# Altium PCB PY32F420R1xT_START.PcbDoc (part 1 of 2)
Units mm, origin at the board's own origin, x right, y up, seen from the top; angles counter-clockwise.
Board outline 45 x 98.2 mm, 2 copper layers (Top Layer, Bottom Layer), stack 0.533 mm thick; 144 components, 163 nets, 571 pads, 318 vias.
Unrouted connection lines stored in the file: 5.
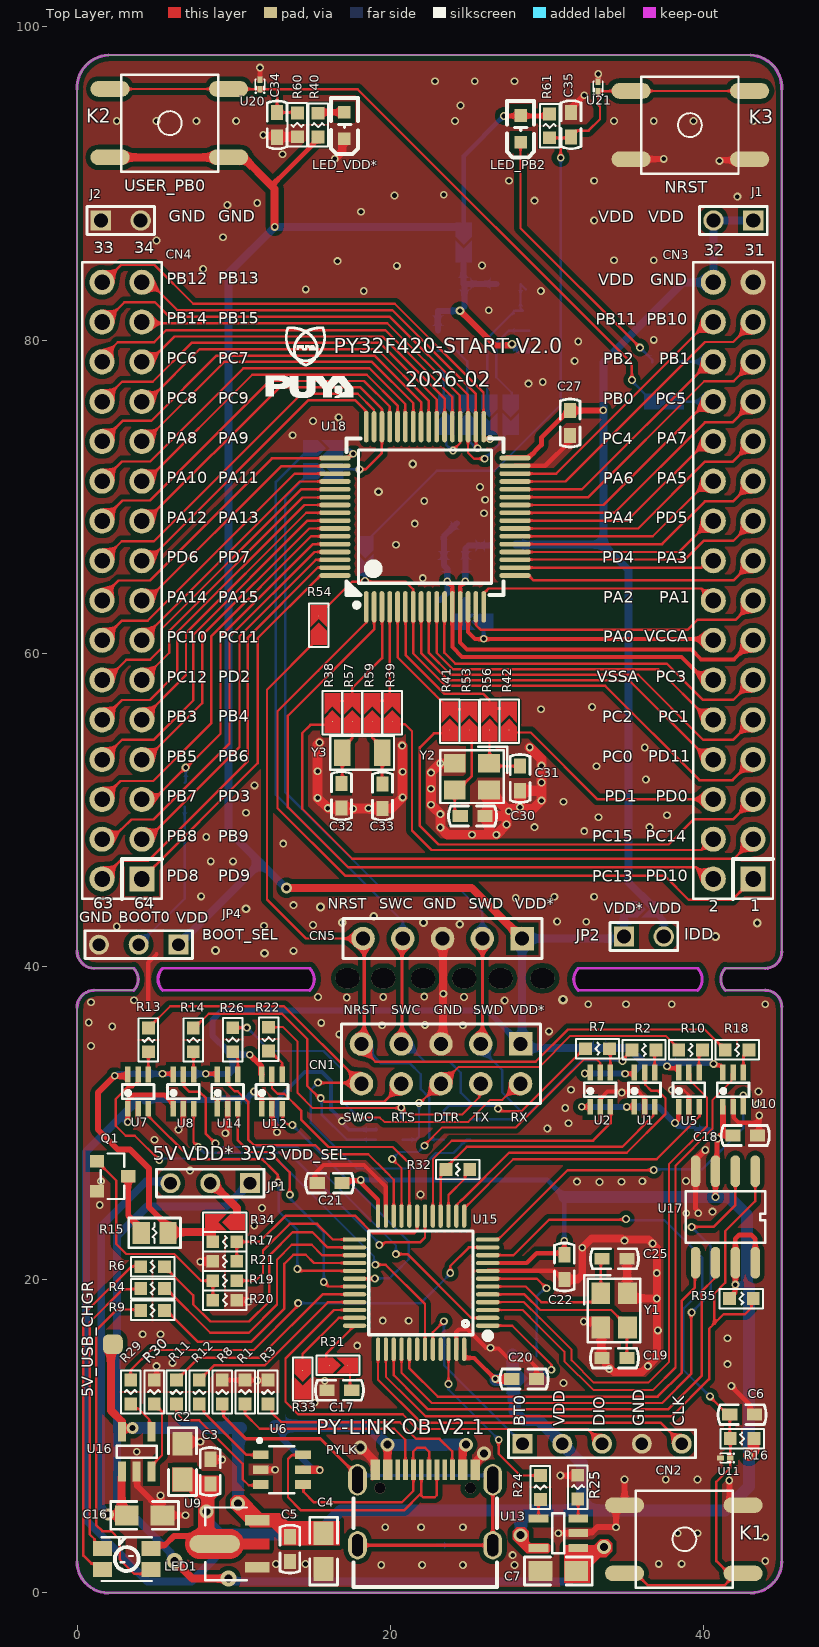
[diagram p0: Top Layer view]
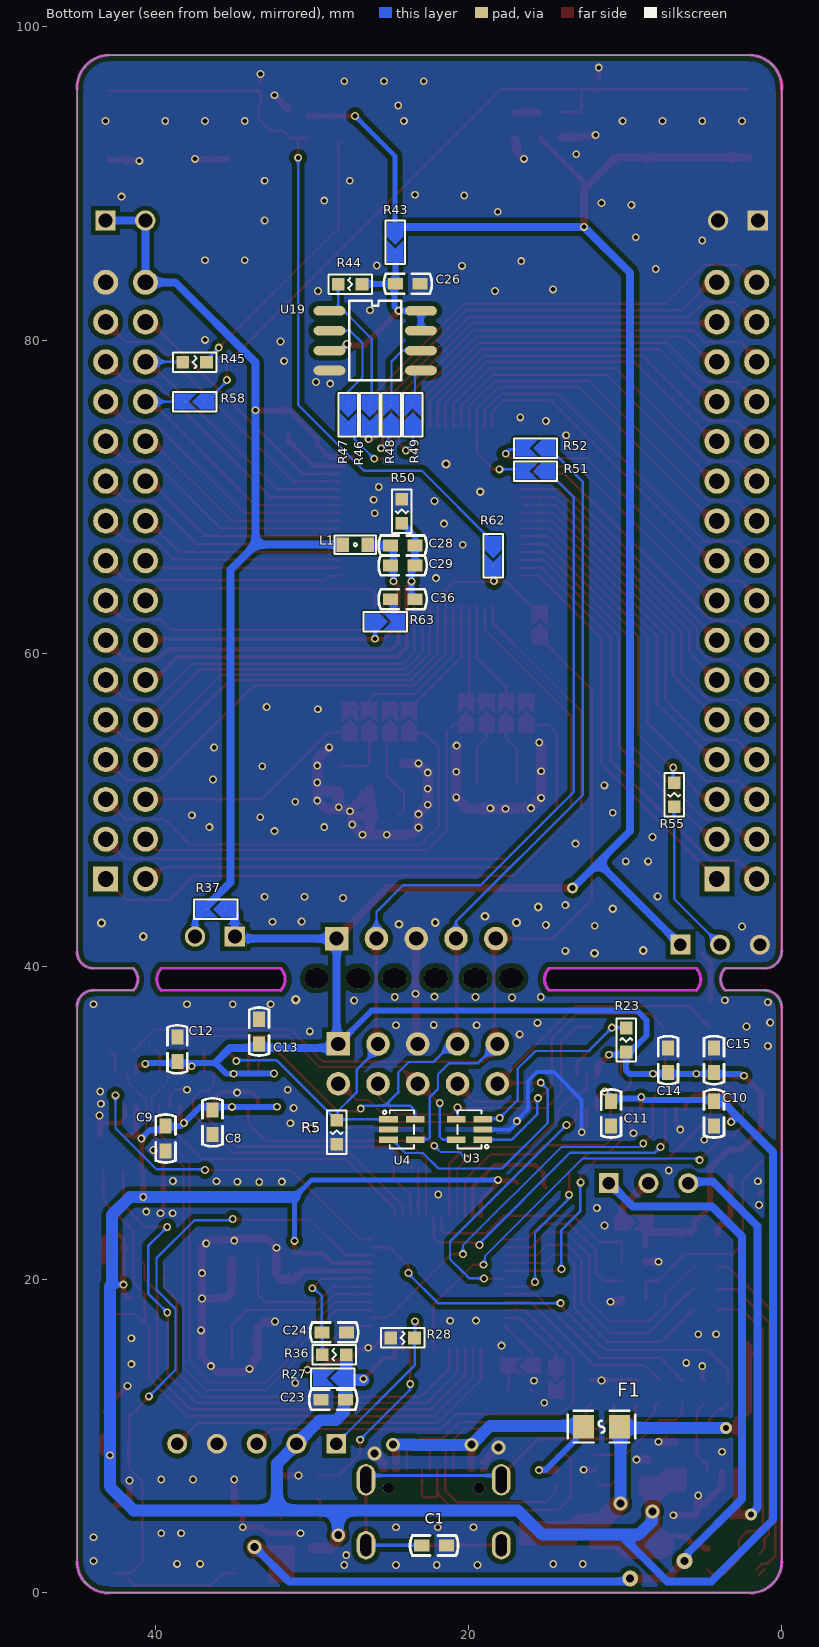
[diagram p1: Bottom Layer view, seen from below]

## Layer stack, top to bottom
Top Solder: solder mask 0.0102, Solder Resist, Dk 3.5
Top Layer: signal copper 0.0356
Dielectric 2: prepreg 0.0711, Composite dielectric, Dk 4.1
Dielectric 1: prepreg 0.32, Composite dielectric, Dk 4.1
Dielectric 3: prepreg 0.0711, Composite dielectric, Dk 4.1
Bottom Layer: signal copper 0.0356
Bottom Solder: solder mask 0.0102, Solder Resist, Dk 3.5

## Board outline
0,2 0,37.338 cw(c1.111,37.37) 1.079,38.481 3.619,38.481 ccw(c2.921,39.179) 3.619,39.878 1.079,39.878 cw(c1.111,40.989) 0,41.021 0,96 cw(c2.099,96.099) 2,98.198 43,98.198 cw(c42.901,96.099) 45,96 45,40.936 cw(c43.942,40.936) 43.942,39.878 41.402,39.878 ccw(c42.1,39.179) 41.402,38.481 43.942,38.481 cw(c43.942,37.423) 45,37.423 45,2 cw(c43,2) 43,0 2,0 cw(c2,2)
cut-out: 5.461,38.481 cw(c6.159,39.179) 5.461,39.878 14.859,39.878 cw(c14.16,39.179) 14.859,38.481 14.351,38.481
cut-out: 32.004,38.481 cw(c32.703,39.179) 32.004,39.878 39.624,39.878 cw(c38.925,39.179) 39.624,38.481

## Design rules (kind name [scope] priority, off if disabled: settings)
Clearance polygon [InPolygon] p1: gap=0.305 ignorepadtopadclearanceinfootprint=TRUE
Clearance [All] p2: gap=0.178 ignorepadtopadclearanceinfootprint=TRUE
HoleToHoleClearance [All] p1: gap=0.025 allowstackedmicrovias=TRUE
MinimumSolderMaskSliver [All] p1: minsoldermaskwidth=0
PlaneClearance [All] p1: clearance=0.203
PlaneConnect [All] p1: planeconnectstyle=Direct reliefexpansion=0.508 reliefentries=4 reliefconductorwidth=0.254 reliefairgap=0.254
PolygonConnect [All] p1: connectstyle=Direct reliefconductorwidth=0.254 reliefentries=4 polygonreliefangle="90 Angle" airgapwidth=0.254
RoutingVias [All] p1: holewidth=0.711 width=1.27 viastyle="Through Hole" minholewidth=0.711 minwidth=1.27 maxholewidth=0.711 maxwidth=1.27
SilkToSilkClearance [All] p1: silktosilkclearance=0
SilkToSolderMaskClearance [IsPad] p1: minsilkscreentomaskgap=0 clearancetoexposedcopper=TRUE
SolderMaskExpansion [All] p1: expansion=0.102 istentingtop=FALSE
UnRoutedNet [All] p1: checkbadconnections=TRUE
Width [All] p1: maxlimit=2.54 minlimit=0.127 preferedwidth=0.203
23 further rules are at their usual default settings.

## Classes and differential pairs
component class PY32F420R1xT_START: C26 C27 C28 C29 C30 C31 C32 C33 C34 C35 C36 CN3 CN4 CN5 J1 J2 JP2 JP4 K2 K3 L1 LED_PB2 LED_VDD* R37 R38 R39 R40 R41 R42 R43 R44 R45 R46 R47 R48 R49 R50 R51 R52 R53 R54 R55 R56 R57 R58 R59 R60 R61 R62 R63 U18 U19 U20 U21 Y2 Y3
component class PY32F403C1xT_LINK: 5V_USB_CHGR C1 C2 C3 C4 C5 C6 C7 C8 C9 C10 C11 C12 C13 C14 C15 C16 C17 C18 C19 C20 C21 C22 C23 C24 C25 CN1 CN2 F1 JP1 K1 LED1 PYLK Q1 R1 R2 R3 R4 R5 R6 R7 R8 R9 R10 R11 R12 R13 R14 R15 R16 R17 R18 R19 R20 R21 R22 R23 R24 R25 R26 R27 R28 R29 R30 R31 R32 R33 R34 R35 R36 U1 U2 U3 U4 U5 U6 U7 U8 U9 U10 U11 U12 U13 U14 U15 U16 U17 Y1

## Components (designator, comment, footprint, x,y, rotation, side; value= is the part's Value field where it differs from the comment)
5V_USB_CHGR "TP_SIN" TP_SIN 2.286,15.875 r90 top
C1 "4.7nF" C0603 22.2,3.023 r0 bottom
C2 "10uF" C0805 6.731,8.382 r270 top
C3 "100nF" C0603 8.509,7.747 r270 top
C4 "10uF" C0805 15.748,2.667 r90 top
C5 "100nF" C0603 13.589,2.794 r90 top
C6 "100nF" C0603 42.469,11.379 r180 top
C7 "10uF" C0805 30.734,1.397 r0 top
C8 "100nF" C0603 36.347,30.048 r90 bottom value=104
C9 "100nF" C0603 39.342,29.014 r90 bottom value=104
C10 "100nF" C0603 4.323,30.604 r90 bottom value=104
C11 "100nF" C0603 10.897,30.604 r90 bottom value=104
C12 "100nF" C0603 38.593,34.712 r270 bottom value=104
C13 "100nF" C0603 33.371,35.842 r270 bottom value=104
C14 "100nF" C0603 7.252,34.016 r270 bottom value=104
C15 "100nF" C0603 4.331,34.016 r270 bottom value=104
C16 "10uF" C0805 4.318,4.953 r180 top
C17 "100nF" C0603 16.754,12.941 r0 top
C18 "100nF" C0603 42.672,29.21 r180 top value=104
C19 "22pF" C0603 34.318,14.986 r0 top
C20 "100nF" C0603 28.546,13.655 r180 top value=104
C21 "100nF" C0603 16.129,26.162 r0 top value=104
C22 "100nF" C0603 31.118,20.803 r90 top value=104
C23 "100nF" C0603 28.644,12.334 r180 bottom value=104
C24 "100nF" C0603 28.578,16.637 r0 bottom value=104
C25 "22pF" C0603 34.318,21.336 r180 top
C26 "100nF" C0603 23.876,83.591 r0 bottom value=104
C27 "100nF" C0603 31.488,74.701 r90 top value=104
C28 "1uF" C0603 24.206,66.878 r0 bottom
C29 "100nF" C0603 24.206,65.608 r0 bottom
C30 "22pF" C0603 25.258,49.607 r180 top
C31 "22pF" C0603 28.291,52.003 r90 top
C32 "22pF" C0603 16.886,50.898 r90 top
C33 "22pF" C0603 19.507,50.873 r90 top
C34 "100nF" C0603 12.776,93.739 r90 top
C35 "100nF" C0603 31.547,93.751 r270 top
C36 "1uF" C0603 24.206,63.449 r0 bottom
CN1 "2X5P" HDR2X5 28.321,35.052 r180 top
CN2 "CON5" CON5 28.448,9.525 r0 top
CN3 "2X16P 2.54mm" HDR-TH_32P-P2.54-V-M-R2-C16-S2.54-3 41.9,64.637 r90 top locked
CN4 "2X16P 2.54mm" HDR-TH_32P-P2.54-V-M-R2-C16-S2.54-3 2.871,64.637 r90 top locked
CN5 "Header 5" HDR1X5 28.421,41.783 r180 top locked
F1 "JK-SMD0805-050-16V" F0805 11.506,10.617 r180 bottom
J1 "CON2" CON2 43.18,87.63 r180 top
J2 "CON2" CON2 1.524,87.63 r0 top
JP1 "CON3" CON3 11.049,26.162 r180 top
JP2 "CON2" CON2 34.925,41.91 r0 top
JP4 "CON3" CON3 6.477,41.391 r180 top
K1 "TS-KG02S-AT43F" SW-SMD_4P-L6.0-W6.0-P4.50-LS8.5 38.8,3.421 r180 top
K2 "TS-KG02S-AT43F" SW-SMD_4P-L6.0-W6.0-P4.50-LS8.5 5.944,93.845 r180 top
K3 "TS-KG02S-AT43F" SW-SMD_4P-L6.0-W6.0-P4.50-LS8.5 39.116,93.726 r0 top
L1 "BEAD" L0603 27.229,66.929 r180 bottom value=600R@100MHz
LED1 "MHPA3528RGBCT" LED-ARRAY-SMD_4P-L3.5-W2.8-TL 3.175,2.159 r0 top
LED_PB2 "GREEN" 0603_LED 28.346,93.853 r90 top
LED_VDD* "RED" 0603_LED 17.094,94.056 r90 top
PYLK "KH-TYPE-C-16P" USB-C-SMD_KH-TYPE-C-16P 22.23,5.456 r0 top locked
Q1 "2302" SOT23 2.27,26.604 r90 top value=SI2302
R1 "5.1K" R0603 10.731,12.827 r270 top
R2 "27R" R0603 36.2,34.671 r180 top
R3 "5.1K" R0603 12.192,12.827 r90 top
R4 "680R" R0603 4.826,19.431 r0 top
R5 "1M" R0603 28.423,29.413 r90 bottom
R6 "680R" R0603 4.826,20.828 r0 top
R7 "27R" R0603 33.233,34.75 r180 top
R8 "1M" R0603 9.271,12.827 r90 top
R9 "680R" R0603 4.826,18.034 r0 top
R10 "27R" R0603 39.176,34.671 r180 top
R11 "27R" R0603 6.35,12.827 r90 top
R12 "27R" R0603 7.81,12.827 r90 top
R13 "27R" R0603 4.563,35.308 r90 top
R14 "27R" R0603 7.424,35.309 r90 top
R15 "100R" R0805 4.953,22.987 r0 top
R16 "10K" R0603 42.469,9.855 r0 top
R17 "20K" R0603 9.437,22.418 r180 top
R18 "27R" R0603 42.151,34.671 r180 top
R19 "100R" R0603 9.437,19.933 r0 top
R20 "100K" R0603 9.437,18.691 r180 top
R21 "10K" R0603 9.437,21.176 r0 top
R22 "27R" R0603 12.233,35.36 r90 top
R23 "4.7K" R0603 9.931,35.306 r270 bottom
R24 "4.7K" R0603 29.591,6.731 r270 top
R25 "16K" R0603 31.979,6.756 r270 top
R26 "27R" R0603 9.936,35.324 r90 top
R27 "0R" JP2_SMD 28.66,13.712 r180 bottom
R28 "10K" R0603 24.206,16.281 r0 bottom
R29 "4.7K" R0603 3.429,12.827 r270 top
R30 "16K" R0603 4.928,12.827 r270 top
R31 "0R" JP2_SMD 16.668,14.522 r180 top
R32 "680R" R0603 24.32,27.035 r0 top
R33 "0R" JP2_SMD 14.401,13.65 r90 top
R34 "0R" JP2_SMD 9.437,23.661 r0 top
R35 "100K" R0603 42.418,18.796 r180 top
R36 "10K" R0603 28.575,15.215 r180 bottom
R37 "0R" JP2_SMD 36.144,43.663 r180 bottom
R38 "0R" JP2_SMD 16.312,56.189 r270 top
R39 "0R" JP2_SMD 20.137,56.189 r270 top
R40 "680R" R0603 15.392,93.726 r270 top
R41 "0R" JP2_SMD 23.8,55.651 r270 top
R42 "0R" JP2_SMD 27.584,55.651 r270 top
R43 "0R/NC" JP2_SMD 24.689,86.233 r90 bottom
R44 "100K" R0603 27.559,83.566 r180 bottom
R45 "680R" R0603 37.49,78.588 r0 bottom
R46 "0R/NC" JP2_SMD 26.314,75.229 r90 bottom
R47 "0R/NC" JP2_SMD 27.686,75.229 r90 bottom
R48 "0R/NC" JP2_SMD 24.943,75.228 r270 bottom
R49 "0R/NC" JP2_SMD 23.571,75.228 r270 bottom
R50 "0R" R0603 24.257,69.063 r90 bottom
R51 "100R" JP2_SMD 15.723,71.628 r180 bottom
R52 "100R" JP2_SMD 15.723,73.101 r180 bottom
R53 "0R" JP2_SMD 25.043,55.646 r270 top
R54 "0R" JP2_SMD 15.443,61.798 r270 top
R55 "10K" R0603 6.871,50.964 r90 bottom
R56 "0R" JP2_SMD 26.34,55.651 r270 top
R57 "0R" JP2_SMD 17.585,56.189 r270 top
R58 "0R" JP2_SMD 37.49,76.073 r180 bottom
R59 "0R" JP2_SMD 18.847,56.189 r270 top
R60 "1.5K" R0603 14.072,93.739 r90 top
R61 "10K" R0603 30.175,93.675 r270 top
R62 "0R" JP2_SMD 18.415,66.218 r90 bottom
R63 "0R/NC" JP2_SMD 25.324,62.001 r0 bottom
U1 "74LVC1T45DW" SOT363 36.237,32.131 r0 top
U2 "74LVC1T45DW" SOT363 33.406,32.131 r0 top
U3 "ESDALC6V1W5" ESD_SOT323-5L 19.939,29.591 r90 bottom
U4 "ESDALC6V1W5" ESD_SOT323-5L 24.257,29.591 r270 bottom
U5 "74LVC1T45DW" SOT363 39.067,32.131 r0 top locked
U6 "USBLC6-2SC6" SOT23-6 13.081,7.874 r90 top
U7 "74LVC1T45DW" SOT363 3.9,32.004 r0 top locked
U8 "74LVC1T45DW" SOT363 6.789,32.004 r0 top
U9 "LM1117F-3.3" SOT-89-3_L4.5-W2.5-P1.50-LS4.2-BR 10.145,3.124 r0 top
U10 "74LVC1T45DW" SOT363 41.897,32.131 r0 top
U11 "ESDALC6V1-1U2" ESD_ST0201 41.402,8.611 r180 top
U12 "74LVC1T45DW" SOT363 12.449,32.004 r0 top
U13 "MT9700" SOT23-5 30.734,3.81 r90 top
U14 "74LVC1T45DW" SOT363 9.619,32.004 r0 top
U15 "PY32F403C1xT" LQFP-48_L7.0-W7.0-P0.50-LS9.0-BL 21.971,19.812 r90 top locked
U16 "MT9700" SOT23-5 3.81,9.017 r0 top
U17 "P25Q64SH" SOP-8P 41.402,24.003 r180 top value=SST25VF020B
U18 "PY32F420Rx" LQFP-64_L10.0-W10.0-P0.50-LS12.0-BL 22.218,68.716 r0 top locked
U19 "P25Q64SH" SOP-8P 25.959,79.959 r270 bottom value=SST25VF020B
U20 "ESDALC6V1-1U2" ESD_ST0201 11.684,96.317 r90 top
U21 "ESDALC6V1-1U2" ESD_ST0201 33.274,96.19 r90 top
Y1 "24MHz" CRYSTAL-SMD_4P-L3.2-W2.5-BL 34.293,18.034 r270 top
Y2 "24MHz" CRYSTAL-SMD_4P-L3.2-W2.5-BL 25.219,52.119 r180 top
Y3 "32.768KHz" CRYSTAL-SMD_L3.2-W1.5-1 18.209,53.635 r180 top value=32.768kHz

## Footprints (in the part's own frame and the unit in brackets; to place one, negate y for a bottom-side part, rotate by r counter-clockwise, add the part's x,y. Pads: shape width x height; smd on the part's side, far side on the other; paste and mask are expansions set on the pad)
0603_LED [mm]
  rect 0.8x0.8 smd: 1(0.483,0.025) 2(-1.219,0.025)
  silkscreen extent -2.18,-0.84 1.4,0.89
C0603 [mil]
  rect 38x30 smd: 1(-31,0) 2(31,0)
  silkscreen extent -60,-25 60,25
C0805 [mil]
  rect 60x50 smd: 1(-45,0) 2(45,0)
  silkscreen extent -85,-35 85,35
CON2 [mm]
  rect 1.3x1.3 hole 0.9: 1(0,0)
  round 1.3 hole 0.9: 2(2.54,0)
  silkscreen extent -0.89,-0.89 3.43,0.89
CON3 [mil]
  rect 50x50 hole 32: 1(0,0)
  round 50 hole 32: 2(100,0) 3(200,0)
  silkscreen extent -35,-35 235,35
CON5 [mil]
  rect 50x50 hole 32: 1(0,0)
  round 50 hole 32: 2(100,0) 3(200,0) 4(300,0) 5(400,0)
  silkscreen extent -35,-35 435,35
CRYSTAL-SMD_4P-L3.2-W2.5-BL [mm]
  rect 1.4x1.2 smd: 1(-1.1,-0.85) 2(1.1,-0.85) 3(1.1,0.85) 4(-1.1,0.85)
  silkscreen extent -2.26,-1.91 2.03,1.68
CRYSTAL-SMD_L3.2-W1.5-1 [mm]
  rect 1.05x1.7 smd: 1(-1.275,0) 2(1.275,0)
  silkscreen extent -2.03,-1.08 2.03,1.08
ESD_SOT323-5L [mm]
  rect 0.4x1.2 smd mask+0.05: 1(-0.65,-0.85) 2(0,-0.85) 3(0.65,-0.85) 4(0.65,0.85) 5(-0.65,0.85)
  silkscreen extent -1.23,-1.21 1.23,0.77, body extent -1.15,-1.05 1.15,1.05, height 1.1
ESD_ST0201 [mm]
  rect 0.425x0.33 smd mask+0.05: 1(-0.312,0) 2(0.312,0)
  silkscreen extent -0.55,-0.3 0.33,0.3, body extent -0.34,-0.18 0.34,0.18, height 0.34
F0805 [mm]
  rect 1.335x1.5 smd paste-100 mask+0.051: 1(-1.142,0) 2(1.142,0)
  silkscreen extent -2.16,-1.02 2.16,1.02
HDR1X5 [mm] "Connector; Header; 5 Position"
  rect 1.5x1.5 hole 0.9: 1(0,0)
  round 1.5 hole 0.9: 2(2.54,0) 3(5.08,0) 4(7.62,0) 5(10.16,0)
  silkscreen extent -1.27,-1.27 11.43,1.27
HDR2X5 [mm] "Connector; Header; 4x2 Position"
  rect 1.5x1.5 hole 0.9: 1(0,0)
  round 1.5 hole 0.9: 2(0,2.54) 3(2.54,0) 4(2.54,2.54) 5(5.08,0) 6(5.08,2.54) 7(7.62,0) 8(7.62,2.54) 9(10.16,0) 10(10.16,2.54)
  silkscreen extent -1.27,-1.27 11.43,3.81
HDR-TH_32P-P2.54-V-M-R2-C16-S2.54-3 [mm]
  rect 1.6x1.6 hole 1: 1(-19.05,-1.27)
  round 1.6 hole 1: 2(-19.05,1.27) 3(-16.51,-1.27) 4(-16.51,1.27) 5(-13.97,-1.27) 6(-13.97,1.27) 7(-11.43,-1.27) 8(-11.43,1.27) 9(-8.89,-1.27) 10(-8.89,1.27) 11(-6.35,-1.27) 12(-6.35,1.27) 13(-3.81,-1.27) 14(-3.81,1.27) 15(-1.27,-1.27) 16(-1.27,1.27) 17(1.27,-1.27) 18(1.27,1.27) 19(3.81,-1.27) 20(3.81,1.27) 21(6.35,-1.27) 22(6.35,1.27) 23(8.89,-1.27) 24(8.89,1.27) 25(11.43,-1.27) 26(11.43,1.27) 27(13.97,-1.27) 28(13.97,1.27) 29(16.51,-1.27) 30(16.51,1.27) 31(19.05,-1.27) 32(19.05,1.27)
  silkscreen extent -20.32,-2.54 20.32,2.54
JP2_SMD [mil]
  round 1 smd: 1(21.75,0) 2(-23.03,0.03)
  Top Layer region: -49.77,20.03 -49.77,20.03 3.72,20.03 -16.28,0.03 3.72,-19.98 -49.78,-19.98 -49.78,-19.98
  Top Layer region: -6.25,0 13.75,20 49.75,20 49.75,-20 49.75,-20 13.75,-20
  silkscreen extent -55,-25 54,25
L0603 [mm]
  rect 0.8x0.95 smd mask+0.05: 1(-0.8,0) 2(0.8,0)
  silkscreen extent -1.33,-0.6 1.33,0.6, body extent -0.87,-0.47 0.87,0.47, height 0.95
LED-ARRAY-SMD_4P-L3.5-W2.8-TL [mm]
  rect 1.2x0.95 smd: 1(1.55,0.665) 2(1.55,-0.665) 3(-1.55,-0.665) 4(-1.55,0.665)
  silkscreen extent -1.6,-1.4 1.6,1.4
LQFP-48_L7.0-W7.0-P0.50-LS9.0-BL [mm]
  oval 0.27x1.5 smd mask+0.05: 1(-2.75,-4.25) 2(-2.25,-4.25) 3(-1.75,-4.25) 4(-1.25,-4.25) 5(-0.75,-4.25) 6(-0.25,-4.25) 7(0.25,-4.25) 8(0.75,-4.25) 9(1.25,-4.25) 10(1.75,-4.25) 11(2.25,-4.25) 12(2.75,-4.25) 25(2.75,4.25) 26(2.25,4.25) 27(1.75,4.25) 28(1.25,4.25) 29(0.75,4.25) 30(0.25,4.25) 31(-0.25,4.25) 32(-0.75,4.25) 33(-1.25,4.25) 34(-1.75,4.25) 35(-2.25,4.25) 36(-2.75,4.25)
  oval 1.5x0.27 smd mask+0.05: 13(4.25,-2.75) 14(4.25,-2.25) 15(4.25,-1.75) 16(4.25,-1.25) 17(4.25,-0.75) 18(4.25,-0.25) 19(4.25,0.25) 20(4.25,0.75) 21(4.25,1.25) 22(4.25,1.75) 23(4.25,2.25) 24(4.25,2.75) 37(-4.25,2.75) 38(-4.25,2.25) 39(-4.25,1.75) 40(-4.25,1.25) 41(-4.25,0.75) 42(-4.25,0.25) 43(-4.25,-0.25) 44(-4.25,-0.75) 45(-4.25,-1.25) 46(-4.25,-1.75) 47(-4.25,-2.25) 48(-4.25,-2.75)
  silkscreen extent -3.59,-4.46 3.3,3.34
LQFP-64_L10.0-W10.0-P0.50-LS12.0-BL [mm]
  oval 0.3x2 smd: 1(-3.75,-5.75) 2(-3.25,-5.75) 3(-2.75,-5.75) 4(-2.25,-5.75) 5(-1.75,-5.75) 6(-1.25,-5.75) 7(-0.75,-5.75) 8(-0.25,-5.75) 9(0.25,-5.75) 10(0.75,-5.75) 11(1.25,-5.75) 12(1.75,-5.75) 13(2.25,-5.75) 14(2.75,-5.75) 15(3.25,-5.75) 16(3.75,-5.75) 33(3.75,5.75) 34(3.25,5.75) 35(2.75,5.75) 36(2.25,5.75) 37(1.75,5.75) 38(1.25,5.75) 39(0.75,5.75) 40(0.25,5.75) 41(-0.25,5.75) 42(-0.75,5.75) 43(-1.25,5.75) 44(-1.75,5.75) 45(-2.25,5.75) 46(-2.75,5.75) 47(-3.25,5.75) 48(-3.75,5.75)
  oval 2x0.3 smd: 17(5.75,-3.75) 18(5.75,-3.25) 19(5.75,-2.75) 20(5.75,-2.25) 21(5.75,-1.75) 22(5.75,-1.25) 23(5.75,-0.75) 24(5.75,-0.25) 25(5.75,0.25) 26(5.75,0.75) 27(5.75,1.25) 28(5.75,1.75) 29(5.75,2.25) 30(5.75,2.75) 31(5.75,3.25) 32(5.75,3.75) 49(-5.75,3.75) 50(-5.75,3.25) 51(-5.75,2.75) 52(-5.75,2.25) 53(-5.75,1.75) 54(-5.75,1.25) 55(-5.75,0.75) 56(-5.75,0.25) 57(-5.75,-0.25) 58(-5.75,-0.75) 59(-5.75,-1.25) 60(-5.75,-1.75) 61(-5.75,-2.25) 62(-5.75,-2.75) 63(-5.75,-3.25) 64(-5.75,-3.75)
  silkscreen extent -5,-5.79 5,5
R0603 [mil]
  rect 32x32 smd: 1(-30,0) 2(30,0)
  silkscreen extent -55,-24 54,25
R0805 [mm]
  rect 1.1x1.4 smd: 1(-0.85,0) 2(0.85,0)
  silkscreen extent -1.65,-0.95 1.65,0.95
SOP-8P [mil]
  oval 24x80 smd: 1(-75,-115) 2(-25,-115) 3(25,-115) 4(75,-115) 5(75,115) 6(25,115) 7(-25,115) 8(-75,115)
  silkscreen extent -100,-65 100,65
SOT23 [mm]
  rect 0.8x0.9 smd: 1(0.95,1) 2(-0.95,1) 3(0,-1)
  silkscreen extent -1.45,-0.75 1.45,0.75
SOT23-5 [mil]
  rect 20x50 smd: 1(-37.5,-50) 2(0,-50) 3(37.5,-50) 4(37.5,50) 5(-37.5,50)
  silkscreen extent -50,-15 50,15
SOT23-6 [mm]
  rect 0.55x1 smd: 1(0.95,1.35) 2(0,1.35) 3(-0.95,1.35) 4(-0.95,-1.35) 5(0,-1.35) 6(0.95,-1.35)
  silkscreen extent -1.5,-0.8 1.96,1.52
SOT363 [mm]
  rect 0.35x1 smd: 1(-0.65,-1.1) 2(0,-1.1) 3(0.65,-1.1) 4(0.65,1.1) 5(0,1.1) 6(-0.65,1.1)
  silkscreen extent -1.02,-0.45 1.02,0.45, body extent -1,-1.1 1,1.16, height 1
SOT-89-3_L4.5-W2.5-P1.50-LS4.2-BR [mm]
  rect 1.575x0.672 smd: 1(1.356,-1.5) 3(1.356,1.5)
  oval 3.226x1.14 smd: 2(-1.356,0)
  Top Layer region: -2.283,0.95 -0.429,0.95 -0.384,0.949 -0.34,0.946 -0.296,0.94 -0.252,0.933 -0.208,0.924 -0.165,0.912 -0.123,0.899 -0.081,0.884 -0.04,0.866 0,0.847 0.04,0.826 0.078,0.803 0.115,0.779 0.151,0.752 0.185,0.724 0.219,0.695 0.251,0.664 0.281,0.631 0.31,0.597 0.337,0.562 0.362,0.525 0.386,0.488 0.408,0.449 0.428,0.409 0.447,0.33 2.144,0.33 2.144,-0.33 0.447,-0.33 0.428,-0.409 0.408,-0.449 0.386,-0.488 0.362,-0.526 0.337,-0.562 0.31,-0.597 0.281,-0.631 0.251,-0.664 0.219,-0.695 0.185,-0.725 0.151,-0.753 0.115,-0.779 0.078,-0.804 0.04,-0.827 0,-0.848 -0.04,-0.867 -0.081,-0.884 -0.123,-0.899 -0.165,-0.913 -0.208,-0.924 -0.252,-0.934 -0.296,-0.941 -0.34,-0.946 -0.384,-0.949 -0.429,-0.95 -2.283,-0.95 -2.328,-0.949 -2.372,-0.946 -2.416,-0.941 -2.46,-0.934 -2.504,-0.924 -2.547,-0.913 -2.589,-0.899 -2.631,-0.884 -2.672,-0.867 -2.713,-0.848 -2.752,-0.827 -2.79,-0.804 -2.827,-0.779 -2.863,-0.753 -2.898,-0.725 -2.931,-0.695 -2.963,-0.664 -2.993,-0.631 -3.022,-0.597 -3.049,-0.562 -3.075,-0.526 -3.098,-0.488 -3.12,-0.449 -3.141,-0.409 -3.159,-0.369 -3.175,-0.327 -3.189,-0.285 -3.202,-0.242 -3.212,-0.199 -3.22,-0.155 -3.227,-0.111 -3.231,-0.067 -3.233,-0.022 -3.233,0.022 -3.231,0.067 -3.227,0.111 -3.22,0.155 -3.212,0.199 -3.202,0.242 -3.189,0.285 -3.175,0.327 -3.159,0.369 -3.141,0.409 -3.12,0.449 -3.098,0.488 -3.075,0.525 -3.049,0.562 -3.022,0.597 -2.993,0.631 -2.963,0.664 -2.931,0.695 -2.898,0.724 -2.863,0.752 -2.827,0.779 -2.79,0.803 -2.752,0.826 -2.713,0.847 -2.672,0.866 -2.631,0.884 -2.589,0.899 -2.547,0.912 -2.504,0.924 -2.46,0.933 -2.416,0.94 -2.372,0.946 -2.328,0.949 -2.283,0.95
  silkscreen extent -1.95,-2.33 0.7,2.33
SW-SMD_4P-L6.0-W6.0-P4.50-LS8.5 [mm]
  oval 2.5x1 smd: 1(-3.734,2.177) 2(3.835,2.177) 3(-3.734,-2.184) 4(3.835,-2.184)
  silkscreen extent -3.08,-3.1 3.12,3.09, body extent -4.48,-3 4.52,3, height 8.95
TP_SIN [mm]
  rrect60% 1.27x1.27 smd: 1(0,0)
USB-C-SMD_KH-TYPE-C-16P [mm]
  oval 1.2x2 hole 0.7 slot 1.7 at 90 deg: 1(-4.32,1.765) 2(4.32,1.765)
  oval 1.2x1.8 hole 0.7 slot 1.4 at 90 deg: 3(-4.32,-2.415) 4(4.32,-2.415)
  rect 0.3x1.3 smd: A1(-3.35,2.415) A4(-2.55,2.415) A5(-1.25,2.415) A6(-0.25,2.415) A7(0.25,2.415) A8(1.25,2.415) A9(2.55,2.415) A12(3.35,2.415) B1(3.05,2.415) B4(2.25,2.415) B5(1.75,2.415) B6(0.75,2.415) B7(-0.75,2.415) B8(-1.75,2.415) B9(-2.25,2.415) B12(-3.05,2.415)
  round 0.7 hole 0.7 unplated: ""(-2.89,1.235) ""(2.89,1.235)
  silkscreen extent -4.57,-5.08 4.57,0.57

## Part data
C1 C3 C5 C6 C17 C19 C25 C28 C29 C30 C31 C32 C33 C34 C35 C36: library part C0603
C2 C4 C7 C16: library part C0805
C8 C9 C10 C11 C12 C13 C14 C15 C18 C20 C21 C22 C23 C24 C26 C27: library part 贴片高压陶瓷电容, "Capacitor (Semiconductor SIM Model)"
CN1: Color=黑色, Current Rating (Max)=-, JLCPCB Part Class="Extended Part", LCSC Part Name="间距:2.54mm 2x5P 直插 方针", Manufacturer=XFCN(兴飞), Manufacturer Part=PZ254V-12-10P, Operating Temperature Range=-40℃~+105℃
CN3 CN4: Color=黑色, Current Rating (Max)=3A, JLCPCB Part Class="Extended Part", LCSC Part Name="2x16P 间距:2.54mm 方针", Manufacturer="XKB Connection(中国星坤)", Manufacturer Part=X6522WV-2x16H-C60D30-E80, Operating Temperature Range=-40℃~+105℃, Soldering Temperature(Max)=260℃, Voltage Rating (Max)=250V
CN5: "Header, 5-Pin"
F1: Current - Max=100A, Hold Current=500mA, JLCPCB Part Class="Extended Part", LCSC Part Name="6V 0.5A 贴片自恢复", Manufacturer=JK(金科), Operating Temperature=-40℃~+85℃, Power Dissipation=600mW, Resistance - Initial (Ri) (Min)=150mΩ, Resistance - Post Trip (R1) (Max)=850mΩ, Trip Current=1A, Voltage - Max=6V
JP2: library part CON2_DIP
K1 K2 K3: Actuator/Cap Color=黑色, Contact Current=50mA, Insulation Resistance=100MΩ, JLCPCB Part Class=扩展库, LCSC Part Name="6*6*4.3mm 立贴 轻触开关", Manufacturer=HANBO(汉博), Operating Force=250gf, Voltage Rating (DC)=12V
L1: "SMD Chip ferrite bead, 600R@100MHz +/-25%, 350mA, 500mohm DC, 0603, T=0.8mm", Manufacturer=TAI-TECH, Manufacturer_Part_Number=FCM1608KF-601T03
LED1: JLCPCB Part Class=扩展库, LCSC Part Name=RGB三色, Manufacturer=MEIHUA(美华)
LED_PB2 LED_VDD*: library part PDI-E803_Dup1
PYLK: BOM_JLCPCB Part Class="Extended Part", BOM_Manufacturer="Shenzhen Kinghelm Elec"
Q1: library part "MOSFET N", "MOSFET N"
R1 R2 R3 R4 R5 R6 R7 R8 R9 R10 R11 R12 R13 R14 R16 R17 R18 R19 R20 R21 R22 R23 R24 R26 R27 R28 R29 R31 R32 R33 R34 R35 R36 R37 R38 R39 R40 R41 R42 R43 R44 R45 R46 R47 R48 R49 R50 R51 R52 R53 R54 R55 R56 R57 R58 R59 R60 R61 R62 R63: library part R0603
R15: library part R0805
R25 R30: library part R0603_7, "0603WAF1602T5E 16KΩ(1602) ±1%"
U3 U4: "Dual Transil array for ESD protection", Manufacturer=STMICROELECTRONICS
U11 U20 U21: "ESD protection 6V1", Manufacturer=STMICROELECTRONICS
U15: "LQFP48", BOM_Manufacturer=PUYA(普冉)
U17 U19: library part SST25VF010, "SST25VF010"
U18: library part PY32F420Rx_1, "LQFP64", BOM_Manufacturer=PUYA(普冉), BOM_Manufacturer Part=PY32CA00R1x
Y1 Y2: library part ABM8AIG-24.000MHZ-82Z-T, "±20ppm , 12.5pF , T_use: -40°C~125°C", Equivalent Series Resistance (ESR)=50Ω, External load capacitor=8pF, Frequency Stability(Full temperature range)=±50ppm, JLCPCB Part Class="Extended Part", LCSC Part Name="24MHz ±20ppm 8pF", Manufacturer=ABRACON, Normal temperature Frequency Tolerance=±20ppm, Operating Temperature=-40℃~+125℃
Y3: library part XKXGI-SUA-32.768K, "±20ppm , 12.5pF , T_use: -40°C~125°C", External load capacitor=12.5pF, Frequency Stability(Full temperature range)=±30ppm, JLCPCB Part Class="Extended Part", LCSC Part Name="32.768kHz ±20ppm 12.5pF YST310S", Manufacturer=YXC(扬兴晶振), Normal temperature Frequency Tolerance=±20ppm, Operating Temperature=-40℃~+85℃

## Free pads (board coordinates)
  oval 1.524x1.27 hole 1.27 slot 1.524 at 0 deg unplated: 1(17.272,39.243) 1(19.558,39.243) 1(22.098,39.243) 1(24.728,39.243) 1(27.051,39.243) 1(29.718,39.243)

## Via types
v1: diameter 0.5, hole 0.3, Top Layer to Bottom Layer, 156 vias
v2: diameter 0.5, hole 0.3, Top Layer to Bottom Layer, tented both sides, 134 vias
v3: diameter 0.559, hole 0.305, Top Layer to Bottom Layer, 14 vias
v4: diameter 0.889, hole 0.508, Top Layer to Bottom Layer, tented both sides, 8 vias
v5: diameter 0.762, hole 0.381, Top Layer to Bottom Layer, tented both sides, 2 vias
v6: diameter 1.016, hole 0.508, Top Layer to Bottom Layer, tented both sides, 2 vias
v7: diameter 0.61, hole 0.305, Top Layer to Bottom Layer, tented both sides, 1 vias
v8: diameter 0.711, hole 0.381, Top Layer to Bottom Layer, 1 vias

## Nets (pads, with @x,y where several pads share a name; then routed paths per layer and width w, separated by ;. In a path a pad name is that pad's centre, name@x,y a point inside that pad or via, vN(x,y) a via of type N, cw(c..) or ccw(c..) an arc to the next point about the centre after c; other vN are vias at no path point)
3.3V_OUT_EN: R24.1 U15.46 | length 11.3
  Top Layer w0.152: U15.46@23.721,15.562 23.722,15.561 v2(23.724,13.335) v2(23.724,13.335) ; v2(26.924,9.779) 26.924,8.875 28.306,7.493 R24.1@29.591,7.493
  Bottom Layer w0.152: v2(23.724,13.335) 23.732,13.327 23.732,12.971 v2(26.924,9.779)
3V3_PYLK: C2.2 C3.2 C8.2 C9.2 C10.2 C11.2 C18.2 C20.2 C21.2 C22.2 C23.2 CN2.2 LED1.1 R16.2 R27.1 R35.2 R36.2 U1.1 U2.1 U5.1 U7.1 U8.1 U9.2 U10.1 U12.1 U13.5 U14.1 U15.9 U15.24 U15.48 U17.3 U17.7 U17.8 | length 200.5
  Top Layer w0.254: v2(11.307,32.02) 11.415,32.02 11.799,31.636 U12.1@11.799,30.904 ; C21.2@16.916,26.162 C21.2@17.035,26.28 ; C22.2@31.115,21.695 v2(31.115,22.479)
  Top Layer w0.279: v2@18.034,26.289 19.221,25.102 U15.24@19.221,24.062 ; U15.48@24.721,15.562 24.721,15.001 24.726,14.997 25.355,14.997 26.763,13.589 v2@26.8,13.589 ; U15.9@26.221,21.062 28.712,21.062 29.345,21.695 C22.2@31.115,21.695
  Top Layer w0.305: v1(3.235,30.065) 3.25,30.08 U7.1@3.25,30.904 3.25,31.442 3.606,31.798 5.583,31.798 6.139,31.242 U8.1@6.139,30.904 ; U14.1@8.969,30.904 8.991,30.927 8.969,30.949 v2(8.969,31.658) ; C21.2@17.035,26.28 17.068,26.314 18.059,26.314 v2(18.117,26.372) ; v2(32.226,31.039) 32.234,31.031 U2.1@32.756,31.031 ; v2(35.103,31.036) 35.108,31.031 U1.1@35.587,31.031 ; v1(38.177,29.998) 38.417,30.238 U5.1@38.417,31.031 38.394,31.008 U5.1@38.4,31.003 ; v2(40.767,25.273) U17.3@40.767,26.924 40.869,27.026 40.869,28.988 v2(40.891,29.01) ; 41.091,29.21 C18.2@41.885,29.21 ; R35.2@41.656,18.796 42.037,19.177 v2(42.037,19.685) U17.7@42.037,21.082 42.037,22.606 42.291,22.86 43.053,22.86 43.307,22.606 U17.8@43.307,21.082
  Top Layer w0.381: LED1.1@4.725,2.824 4.914,2.824 4.914,2.836 5.134,3.056 5.614,3.056 6.205,3.647 U9.2@7.97,3.647 ; v2(40.891,29.01) 41.091,29.21 41.247,29.366 U10.1@41.247,31.031
  Top Layer w0.508: v2@26.794,13.655 C20.2@27.759,13.655
  Top Layer w0.762: v2(42.901,8.788) 43.205,9.093 43.205,9.83 R16.2@43.231,9.855
  Bottom Layer w0.305: v2(18.117,26.372) 30.016,26.372 31.115,25.273 ; v2(31.115,22.479) 31.115,25.146 ; v2(42.037,19.685) 42.767,19.685 42.79,19.685
  Bottom Layer w0.381: C10.2@4.323,31.392 4.411,31.479 8.79,31.479 v2(8.969,31.658) 9.066,31.562 10.727,31.562 C11.2@10.897,31.392 10.897,31.609 v2(11.307,32.02) v2@11.267,32.06 ; v2(32.226,31.039) 36.347,31.039 37.135,31.039 v1(38.177,29.998) 38.373,29.802 C9.2@39.342,29.802 ; C9.2@39.581,29.563 40.338,29.563 v2(40.891,29.01)
  Bottom Layer w0.508: v1(3.235,30.065) 2.867,30.433 2.836,30.433 ; C10.2@4.323,31.603 4.006,31.603 2.836,30.433 ; 10.294,3.715 7.312,0.733 4.5,0.733 0.559,4.674 0.559,28.156 2.836,30.433 ; v2(26.705,13.665) 27.728,13.665
  Bottom Layer w0.762: v4(8.255,5.207) 8.279,5.183 8.279,4.57 9.134,3.715 10.294,3.715 15.294,3.715 16.845,5.266 28.345,5.266 ; v2@26.712,13.599 27.995,13.599 ; R36.2@27.813,15.215 27.813,14.308 27.813,14.006 R27.1@28.107,13.712 27.995,13.599 ; v4(28.321,3.683) 28.345,3.707 28.345,5.266 ; 31.115,25.273 v2(40.767,25.273) 41.63,25.273 42.767,24.136 42.767,19.685 ; 42.79,19.685 42.901,19.575 v2(42.901,8.788) 42.901,6.786 41.381,5.266 32.233,5.266 ; 27.995,13.599 27.857,13.461 C23.2@27.857,12.334 27.959,12.334 27.959,11.538 28.473,11.024 29.489,11.024 CN2.2@30.988,9.525 30.988,9.5 32.233,8.255 32.233,5.266 ; 28.345,5.266 32.233,5.266
3V3_USB_PYLK: C7.2 JP1.1 U13.1 | length 61.1
  Top Layer w0.508: v6@6.243,2.032 7.367,0.909 v6(9.676,0.909)
  Bottom Layer w0.508: v6(6.223,2.032) 6.223,2.169 5.976,2.417 5.976,2.565 2.543,5.998 2.543,22.755 4.46,24.673 9.515,24.673 10.623,25.781 10.668,25.781 11.004,26.117 JP1.1@11.004,26.162 ; v6(9.676,0.909) 9.851,0.734 31.468,0.734 v4(33.655,2.921) v4@33.7,2.876
5V_OUT_EN: R29.1 U15.11 | length 27.1
  Top Layer w0.152: R29.1@3.429,13.589 3.429,14.224 4.716,15.511 11.288,15.511 14.12,18.343 v2(14.12,18.502) ; v2(23.832,20.423) 23.832,20.875 25.019,22.062 U15.11@26.221,22.062
  Bottom Layer w0.152: v2(14.12,18.502) 21.956,18.502 23.832,20.378 v2(23.832,20.423)
5V_USB_CHGR: 5V_USB_CHGR.1 C4.2 C5.2 F1.2 U9.3 U16.5 | length 18.2
  Top Layer w0.508: 5V_USB_CHGR.1@2.286,15.875 2.164,15.753 2.164,11.646 2.857,10.953 U16.5@2.857,10.287 ; U16.5@2.857,10.492 3.507,10.492 v5(3.556,10.541)
  Bottom Layer w0.762: v5(3.556,10.541) F1.2@10.481,10.541 ; v4(10.287,5.715) F1.2@10.287,10.347
5V_USB_PYLK: C16.2 JP1.3 U16.1 | length 28.2
  Top Layer w0.508: v5(1.966,4.999) 1.989,4.976 3.152,4.976 C16.2@3.175,4.953 ; U16.1@2.857,7.739 2.857,7.366 2.85,7.358 2.85,5.334 C16.2@3.175,5.334
  Bottom Layer w0.508: v5(1.966,4.999) 1.903,5.012 1.809,5.106 1.773,5.142 1.547,5.48 1.547,23.416 4.39,26.259 5.872,26.259 JP1.3@5.969,26.162
AD_TVDD: R17.1 R21.2 U15.19 | length 14.9
  Top Layer w0.152: R21.2@10.199,21.176 R17.1@10.199,22.418 11.653,22.418 13.309,24.074 17.771,24.074 18.887,22.958 21.51,22.958 21.721,23.169 U15.19@21.721,24.062
BOOT0: CN4.5 R55.2 U18.60 | length 23.7
  Top Layer w0.152: CN4.5@4.141,50.667 4.902,50.667 v1(6.933,52.698) 7.002,52.698 9.161,54.857 9.161,61.069 15.058,66.966 U18.60@16.468,66.966
  Bottom Layer w0.152: R55.2@6.871,51.726 6.943,51.798 v1@6.943,52.689
DIR_RESET: U10.5 U15.3 | length 35.4
  Top Layer w0.127: U15.3@26.221,18.062 28.465,18.062 29.465,17.062 31.121,15.406 31.121,14.802 32.963,12.96 36.782,12.96 38.215,14.392 38.215,27.281 40.563,29.628 40.563,31.457 41.786,32.679 41.786,33.119 U10.5@41.897,33.231
DIR_RTCK_DTR: U5.5 U15.4 | length 34.6
  Top Layer w0.127: U15.4@26.221,18.562 28.542,18.562 29.542,17.562 31.583,15.521 31.583,14.846 32.997,13.432 36.473,13.432 37.809,14.768 37.809,27.389 40.233,29.813 40.233,31.625 39.178,32.68 39.178,33.119 U5.5@39.067,33.231
DIR_TCK_SWCLK: U2.5 U15.21 | length 20.5
  Top Layer w0.127: v2(20.12,27.703) 20.721,27.102 U15.21@20.721,24.062 ; v1(22.187,28.553) 22.187,28.589 23.3,29.703 27.999,29.703 30.904,32.608 32.344,34.048 33.203,34.048 33.406,33.844 U2.5@33.406,33.231
  Bottom Layer w0.127: v2(20.12,27.703) 20.564,28.147 21.781,28.147 v1(22.187,28.553)
DIR_TDI_VCP_TX: U12.5 U15.20 | length 15.3
  Top Layer w0.152: U12.5@12.449,33.104 12.449,32.227 12.799,31.876 13.233,31.876 14.307,30.802 14.307,30.224 16.056,28.475 20.159,28.475 21.221,27.413 U15.20@21.221,24.062
DIR_TDO_SWO: U7.5 U15.43 | length 31.8
  Top Layer w0.152: U7.5@3.9,33.104 3.9,32.632 3.561,32.293 3.231,32.293 2.474,31.536 2.474,29.827 3.111,29.19 3.689,29.19 v1(5.246,27.633) ; v2(19.05,20.955) 19.702,20.955 22.221,18.437 U15.43@22.221,15.562
  Bottom Layer w0.127: v1(5.246,27.633) 5.361,27.747 12.705,27.747 18.958,21.495 18.958,21.047 v2(19.05,20.955)
DIR_TMS_SWDIO: U1.5 U15.14 | length 19.9
  Top Layer w0.152: U15.14@24.221,24.062 24.221,24.739 24.307,24.825 24.307,24.849 24.549,25.091 24.573,25.091 27.588,28.106 35.098,28.106 37.577,30.585 37.577,31.581 37.104,32.054 36.672,32.054 36.284,32.442 36.284,33.183 U1.5@36.237,33.231
DIR_TRST_RTS: U8.5 U15.2 | length 28
  Top Layer w0.152: U8.5@6.789,33.104 6.803,33.089 6.803,32.366 7.176,31.993 7.827,31.993 8.228,31.591 8.228,29.306 v2(8.841,28.694) ; v2(20.359,21.633) 21.1,21.633 25.171,17.562 U15.2@26.221,17.562
  Bottom Layer w0.127: v2(8.841,28.694) 9.051,28.484 14.061,28.484 20.359,22.186 v2(20.359,21.633)
DIR_VCP_RX: U14.5 U15.22 | length 17.5
  Top Layer w0.152: U14.5@9.619,33.104 9.654,33.069 9.654,32.439 10.074,32.019 10.267,32.019 10.922,31.364 10.922,28.957 11.293,28.586 15.222,28.586 15.8,28.009 18.597,28.009 19.72,26.886 20.221,26.385 U15.22@20.221,24.062
F_VDD: C26.2 R43.2 R44.2 U19.3 U19.7 U19.8 | length 14
  Top Layer w0.381: v3(24.46,81.864) 26.664,79.66 27.691,79.66 v3(27.768,79.737)
  Bottom Layer w0.381: U19.7@23.038,80.594 U19.8@23.038,81.864 v3(24.46,81.864) 24.74,82.144 24.74,83.515 C26.2@24.663,83.591 ; R43.2@24.689,85.648 24.663,85.622 C26.2@24.663,83.591 ; R44.2@26.797,83.566 26.772,83.591 C26.2@24.663,83.591 ; v3(27.768,79.737) U19.3@27.978,79.528 ; U19.3@28.181,79.324 U19.3@28.88,79.324
GND: C1.1 C2.1 C3.1 C4.1 C5.1 C6.1 C7.1 C8.1 C9.1 C10.1 C11.1 C12.1 C13.1 C14.1 C15.1 C16.1 C17.1 C18.1 C19.1 C20.1 C21.1 C22.1 C23.1 C24.1 C25.1 C26.1 C27.1 C30.1 C31.1 C32.1 C33.1 C34.1 C35.1 CN1.5 CN2.4 CN3.31 CN5.3 J2.1 J2.2 JP4.3 K1.3 K1.4 K3.3 K3.4 LED_VDD*.2 PYLK.A1 PYLK.A12 PYLK.B1 PYLK.B12 Q1.2 R1.1 R3.2 R5.1 R8.2 R20.1 R21.1 R25.1 R28.2 R30.1 R33.2 R50.2 R60.1 U1.2 U2.2 U3.2 U4.2 U5.2 U6.2 U7.2 U8.2 U9.1 U10.2 U11.2 U12.2 U13.2 U14.2 U15.8 U15.23 U15.47 U16.2 U17.4 U18.31 U19.4 U20.2 U21.2 Y1.2 Y1.4 Y2.2 Y2.4 | length 173.5
  Top Layer w0.152: v2(37.973,32.131) 38.735,32.131 39.067,31.799 U5.2@39.067,31.031
  Top Layer w0.254: U7.2@3.9,30.904 U7.2@3.919,30.886 ; R30.1@4.953,13.589 5.08,13.716 v2(5.08,14.478) ; C16.1@5.334,5.334 5.334,5.08 C16.1@5.461,4.953 ; v2(6.477,29.581) 6.754,29.857 6.754,30.869 U8.2@6.789,30.904 ; C2.1@6.731,9.525 C2.1@6.858,9.652 ; C3.1@8.509,8.534 C3.1@8.534,8.509 ; R8.2@9.271,13.589 v2@11.53,13.589 ; v2(9.472,29.355) 9.616,29.499 U14.2@9.616,30.901 ; R20.1@10.199,18.691 R20.1@10.237,18.73 ; v2(11.509,13.568) v2@11.53,13.589 ; U20.2@11.684,96.629 v2(11.684,97.391) ; R3.2@12.192,13.589 v2@11.53,13.589 ; U12.2@12.449,30.904 12.482,30.871 12.482,29.784 12.746,29.52 12.746,29.383 v2@12.7,29.337 ; C21.1@15.071,25.908 15.325,26.162 C21.1@15.342,26.162 15.188,26.316 15.188,26.775 15.728,27.316 18.338,27.316 19.223,26.431 ; C17.1@15.966,12.941 C17.1@15.992,12.967 ; PYLK.A1@18.88,7.871 PYLK.B12@19.18,7.871 ; PYLK.B1@25.28,7.871 PYLK.A12@25.58,7.871 ; v2@26.403,15.584 v2@26.406,15.588 ; v2@26.457,15.596 26.908,15.596 27.65,14.854 28.881,14.854 29.335,14.401 C20.1@29.334,13.655 ; U21.2@33.274,96.451 33.274,96.976 v2(33.28,96.982) ; U2.2@33.382,31.007 33.454,31.079 33.454,31.571 33.887,32.004 v2@34.798,32.004 ; v2(34.778,31.943) 34.798,31.964 v2@34.798,32.004 ; U1.2@36.237,31.031 36.189,31.079 36.189,31.629 35.814,32.004 v2@34.798,32.004 ; U10.2@41.897,31.031 41.945,30.983 41.945,30.326 42.256,30.016 43.561,30.016
  Top Layer w0.279: 4.538,37.858 4.538,40.231 5.076,40.769 ; 19.223,26.431 19.721,25.933 U15.23@19.721,24.062 ; U15.47@24.221,15.562 24.221,16.66 24.377,16.817 24.945,16.817 26.108,15.653 v2(26.4,15.653) ; U15.8@26.221,20.562 30.478,20.562 31.025,20.015 C22.1@31.118,20.015 ; U18.31@27.964,71.97 U18.31@27.967,71.966 29.904,71.966 31.488,73.551 C27.1@31.488,73.914
  Top Layer w0.305: Q1.2@1.275,25.649 Q1.2@1.397,25.527 ; v2(39.667,24.238) 39.798,24.238 39.497,24.539 39.497,27.658 40.117,28.277 v2(40.117,28.283) ; v2(41.783,13.208) 42.971,12.02 42.971,11.608 42.975,11.603 C6.1@43.256,11.603 ; C18.1@43.459,29.21 43.561,29.312 43.561,30.016 v2(43.561,30.48)
  Top Layer w0.381: U16.2@3.797,7.734 3.833,7.697 3.833,6.835 C16.1@5.334,5.334 ; C16.1@5.461,4.953 v2(6.923,4.953) ; v2(11.887,93.091) 11.938,93.04 C34.1@12.776,93.04 ; U6.2@11.955,7.875 11.995,7.835 12.022,7.862 v2(12.651,7.862) ; v2(30.734,3.81) U13.2@32.004,3.81 32.059,3.865 32.884,3.865 33.229,4.21 v2@34.398,4.21 ; v2(30.861,7.493) R25.1@32.004,7.493 ; C35.1@31.496,94.64 31.496,94.742 v2(32.385,95.631) ; v2(34.417,4.191) 34.417,5.32 34.703,5.606 K1.4@34.964,5.606 v2(34.964,7.239) ; K3.3@35.382,91.542 35.395,91.554 37.452,91.554 v2(37.465,91.567) ; v2(41.021,91.44) 41.065,91.484 42.894,91.484 K3.4@42.951,91.542 ; v2(41.652,7.172) 41.652,6.35 41.665,6.337 41.665,5.892 41.951,5.606 K1.3@42.533,5.606
  Top Layer w0.508: C16.1@5.334,5.334 v2(5.334,6.223) ; C2.1@6.858,9.652 v2(7.874,9.652) ; v2(7.87,21.14) 7.889,21.159 8.666,21.159 R21.1@8.685,21.179 ; C3.1@8.534,8.509 v2(9.271,8.509) ; R20.1@10.237,18.73 10.237,18.723 10.351,18.609 10.92,18.609 v2(10.94,18.59) ; C34.1@12.776,92.951 12.802,92.977 R60.1@14.072,92.977 ; v1(16.459,91.567) 16.923,92.031 16.923,92.691 LED_VDD*.2@17.069,92.837 ; v4(18.087,9.271) 18.162,9.271 PYLK.A1@19.029,8.404 ; CN1.5@23.241,35.052 CN1.5@23.431,35.242 ; CN1.5@23.368,35.298 23.368,41.783 CN5.3@23.479,41.672 ; PYLK.A12@25.442,8.334 v4(25.998,8.89) ; C22.1@30.991,20.244 31.118,20.117 C22.1@31.118,20.015 31.125,20.022 31.964,20.022 32.261,20.32 v2(32.261,22.036) 32.866,22.642 34.808,22.642 v2(34.957,22.493) 34.985,22.493 35.063,22.572 36.486,22.572 v2(36.754,22.304) 37.022,22.036 v2(37.022,20.418) 37.022,18.799 37.022,15.048 v2(36.452,14.478) 36.064,14.09 34.287,14.09 v2@34.027,14.351 ; v2(32.359,17.33) 33.047,17.33 Y1.2@33.443,16.934 33.487,16.89 33.487,15.03 C19.1@33.531,14.986 33.633,14.986 33.76,14.859 33.76,14.618 33.791,14.586 ; 33.791,14.494 v2(33.981,14.305) ; C25.1@35.106,21.336 35.124,21.317 35.124,19.153 Y1.4@35.143,19.134 35.477,18.8 v2(37.022,18.8)
  Top Layer w0.635: v1(15.487,54.297) 15.365,54.175 v1(15.365,50.764) v1(16.017,50.111) C32.1@16.886,50.111 16.912,50.085 C33.1@19.507,50.085 20.08,50.085 v1(20.79,50.795) 20.79,54.07 v1(20.76,54.1) ; Y2.2@24.119,52.969 v1(23.193,52.969) v1(22.602,52.378) v1(22.602,50.322) 22.794,50.13 v1(23.199,49.725) v1(23.199,48.872) 23.662,48.408 v1(26.775,48.408) v1(27.429,49.063) v1@27.429,49.771 ; C30.1@26.045,49.607 27.266,49.607 v1@27.429,49.771 ; 26.319,48.584 Y2.4@26.319,51.269 ; Y2.4@26.319,51.155 v1(27.566,49.908) v1@27.429,49.771 ; v1@27.703,50.045 29.113,50.045 v1(29.657,50.59) v1(29.657,51.746) v1(29.657,52.822) 29.657,53.235 v1(28.903,53.99) ; v1(28.291,50.162) C31.1@28.291,51.216 29.61,51.216
  Bottom Layer w0.152: v2@12.681,29.409 v2(12.773,29.409)
  Bottom Layer w0.254: v2(12.773,29.409) 12.773,31.483 14.541,33.25 15.639,33.25 16.205,32.684 16.205,30.881 16.914,30.173 v2(16.914,30.122) ; v2@16.891,30.048 17.367,29.573 19.071,29.573 U3.2@19.089,29.591
  Bottom Layer w0.508: CN1.5@23.241,35.052 CN1.5@23.393,35.204 ; CN5.3@23.341,41.783 CN5.3@23.393,41.731
  other v1: 12.706,1.847 14.592,1.847 15.164,12.141 31.066,13.405 15.818,13.542 6.094,14.686 17.892,15.788 21.174,17.372 19.519,17.386 11.321,23.461 38.896,24.245 40.583,24.343 11.807,24.578 21.934,25.44 33.365,26.24 34.762,26.25 31.919,26.26 36.099,26.28 38.879,26.303 7.214,26.975 4.953,28.931 31.376,29.984 31.171,30.96 43.477,31.236 43.518,32.02 30.139,35.853 2.25,36.17 0.744,36.426 13.818,40.996 2.54,42.545 11.938,42.596 15.062,42.647 32.512,42.85 13.818,43.917 28.016,44.374 30.48,44.45 33.02,44.45 7.925,44.475 8.534,46.711 9.957,46.711 13.164,47.844 8.255,48.26 25.219,48.408 32.385,48.641 29.21,48.895 36.551,48.895 33.299,49.53 37.668,49.657 10.795,49.809 17.643,50.073 18.607,50.101 31.064,50.521 22.602,51.35 11.328,51.562 36.322,51.943 20.79,52.432 15.365,52.469 33.172,52.781 36.246,53.975 29.62,56.422 32.893,56.566 22.073,64.795 20.371,66.929 21.565,68.275 25.984,68.936 22.174,69.723 26.06,69.799 25.73,70.612 13.767,73.914 15.062,74.828 16.703,75.062 28.829,77.216 29.743,77.318 31.775,78.664 32.004,79.908 36.83,80.01 26.287,81.902 18.313,83.134 29.616,83.134 14.605,83.236 8.052,84.531 20.422,84.734 25.857,84.76 16.637,85.039 34.29,85.09 36.83,85.09 5.08,86.36 9.322,86.563 33.02,87.63 18.136,88.189 9.601,88.621 11.506,88.748 29.21,88.9 42.164,89.154 20.271,89.228 23.419,89.281 27.584,90.17 33.02,90.17 13.121,91.861 2.54,93.98 5.08,93.98 7.62,93.98 10.16,93.98 24.13,93.98 34.29,93.98 36.83,93.98 39.37,93.98 43.18,93.98 24.486,94.971 22.86,96.52 25.4,96.52 27.94,96.52
  other v2: 19.431,1.778 22.034,1.778 24.638,1.778 27.94,1.778 37.141,1.854 38.608,1.854 43.942,2.032 27.813,2.413 43.942,3.556 38.354,3.81 39.624,3.81 19.685,4.191 21.971,4.191 24.638,4.191 37.592,7.239 39.624,7.239 3.81,9.017 41.529,14.605 41.529,16.256 4.191,16.51 5.334,16.51 37.087,16.764 1.455,24.774 1.524,26.289 30.032,29.656 31.545,32.13 0.889,34.925 16.739,35.662 19.482,36.246 24.638,36.246 22.225,36.271 15.596,36.398 32.639,37.592 35.052,37.592 37.973,37.592 43.942,37.592 0.889,37.719 27.305,37.821 3.632,37.846 17.221,38.024 15.392,38.049 19.558,38.049 24.714,38.049 22.174,38.075 23.393,38.252 30.658,42.875
  other v3: 11.963,40.843 8.839,41.021 40.767,41.91 24.435,42.697 43.434,42.774 16.942,42.799 22.123,42.799 18.948,43.205 10.795,43.688 15.545,43.79 19.253,70.307 21.438,72.085
  other v7: 31.031,37.882
L_USB_CN_DM: PYLK.A7 PYLK.B7 U6.4 | length 13
  Top Layer w0.152: U6.4@14.431,6.924 14.457,6.898 14.457,6.463 15.139,5.781 20.736,5.781 21.48,6.525 PYLK.B7@21.48,7.871 21.46,7.891 21.46,9.014 21.717,9.271 22.225,9.271 22.48,9.016 PYLK.A7@22.48,7.871
L_USB_CN_DP: PYLK.A6 PYLK.B6 U6.6 | length 17.2
  Top Layer w0.152: U6.6@14.431,8.824 14.408,8.801 13.726,8.801 13.471,8.546 13.471,6.106 14.306,5.271 20.886,5.271 21.909,6.294 21.942,6.327 21.97,6.355 21.975,6.34 ; 21.99,6.279 21.99,6.213 22.004,6.199 22.099,6.104 22.836,6.104 22.97,6.237 PYLK.B6@22.97,7.861 ; 21.99,6.294 PYLK.A6@21.99,7.861
LED_BLUE: R9.2 U15.28 | length 17.1
  Top Layer w0.152: R9.2@5.588,18.034 5.716,18.034 7.703,16.047 11.139,16.047 13.242,18.15 13.242,21.016 13.816,21.59 14.605,21.59 15.133,21.062 U15.28@17.721,21.062
LED_GREEN: R6.2 U15.26 | length 18.4
  Top Layer w0.152: R6.2@5.588,20.828 7.412,19.004 7.412,18.432 8.518,17.326 10.98,17.326 12.28,18.627 12.28,21.551 13.76,23.031 15.034,23.031 16.004,22.062 U15.26@17.721,22.062
LED_RED: R4.2 U15.27 | length 17.6
  Top Layer w0.152: R4.2@5.588,19.431 5.691,19.431 8.51,16.613 10.976,16.613 12.768,18.405 12.768,21.277 13.716,22.225 14.986,22.225 15.649,21.562 U15.27@17.721,21.562
NetC1_2: C1.2 PYLK.1 PYLK.2 PYLK.3 PYLK.4 R8.1 | length 36.5
  Top Layer w0.203: R8.1@9.271,12.065 9.355,11.981 9.355,11.274 10.786,9.843 15.544,9.843 17.91,7.477 PYLK.1@17.91,7.221 ; PYLK.3@17.91,3.041 PYLK.4@26.55,3.041 PYLK.2@26.55,7.221
  Bottom Layer w0.203: PYLK.1@18.187,7.498 PYLK.2@26.273,7.498 ; C1.2@22.987,3.023 23.005,3.041 PYLK.4@26.55,3.041
  Bottom Layer w0.508: PYLK.1@17.91,7.221 PYLK.1@18.187,7.498 ; PYLK.2@26.273,7.498 PYLK.2@26.55,7.221
NetC17_2: C17.2 R31.2 | length 1.6
  Top Layer w0.152: 17.43,14.522 17.43,13.053 C17.2@17.541,12.941
NetC30_2: C30.2 R53.1 Y2.3 | length 6.1
  Top Layer w0.152: C30.2@24.47,49.607 24.119,49.959 Y2.3@24.119,51.269 24.316,51.269 25.21,52.164 25.21,54.727 25.043,54.894
NetC31_2: C31.2 R56.1 Y2.1 | length 4
  Top Layer w0.152: 26.341,54.945 26.341,52.991 Y2.1@26.319,52.969 26.498,52.791 C31.2@28.291,52.791
NetC32_2: C32.2 R57.1 Y3.2 | length 4.5
  Top Layer w0.152: C32.2@16.886,51.686 16.934,51.734 16.934,53.102 16.934,53.924 17.585,54.575 17.585,55.427 ; Y3.2@16.934,53.175 Y3.2@16.934,53.635
NetC33_2: C33.2 R59.1 Y3.1 | length 4.1
  Top Layer w0.152: 18.847,55.44 18.847,54.609 19.484,53.972 Y3.1@19.484,53.635 19.484,51.683 C33.2@19.507,51.66
NetC34_2: C34.2 K2.3 K2.4 R58.1 R60.2 U20.1 | length 46.3
  Top Layer w0.152: K2.4@2.108,96.03 K2.3@9.677,96.03 9.686,96.021 11.558,96.021 U20.1@11.717,95.862 ; U20.1@11.684,96.004 12.751,96.004 ; R60.2@14.072,94.539 12.852,94.539 12.776,94.615 12.776,95.979 12.751,96.004 ; v1(35.433,77.445) 35.433,78.501 17.93,96.004 12.751,96.004
  Bottom Layer w0.152: v1@35.395,77.406 36.728,76.073
NetC35_2: C35.2 K3.1 K3.2 R61.2 R62.1 U21.1 | length 48.5
  Top Layer w0.152: R61.2@30.175,92.913 30.882,92.913 ; v1(30.882,91.634) 30.882,92.913 ; K3.2@42.951,95.903 K3.1@35.382,95.903 35.369,95.89 33.278,95.89 33.274,95.886 33.274,95.027 33.397,94.904 33.397,94.101 32.666,93.37 31.852,93.37 31.547,93.066 C35.2@31.547,92.964 31.496,92.913 30.882,92.913
  Bottom Layer w0.152: 18.4,67.073 22.98,71.653 26.67,71.653 30.882,75.866 v1(30.882,91.634)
